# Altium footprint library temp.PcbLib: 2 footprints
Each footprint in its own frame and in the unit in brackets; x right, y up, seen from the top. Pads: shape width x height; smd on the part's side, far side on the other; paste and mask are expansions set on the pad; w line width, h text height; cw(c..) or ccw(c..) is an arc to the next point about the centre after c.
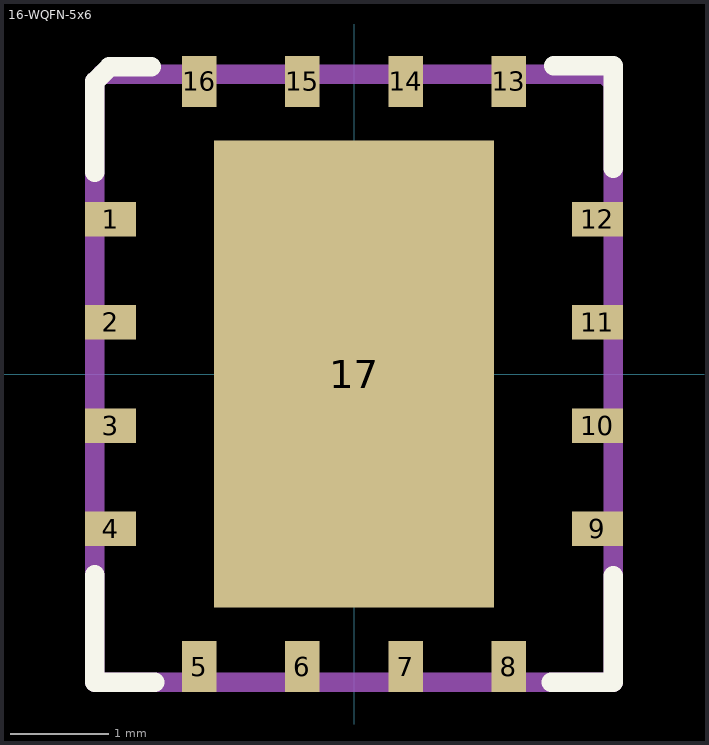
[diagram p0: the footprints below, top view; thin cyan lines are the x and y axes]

## 16-WQFN-5x6 [mm]
pads (17):
  rect 0.52x0.35 smd mask+0.05: 1(-2.475,1.575) 2(-2.475,0.525) 3(-2.475,-0.525) 4(-2.475,-1.575) 9(2.475,-1.575) 10(2.475,-0.525) 11(2.475,0.525) 12(2.475,1.575)
  rect 0.35x0.52 smd mask+0.05: 5(-1.575,-2.975) 6(-0.525,-2.975) 7(0.525,-2.975) 8(1.575,-2.975) 13(1.575,2.975) 14(0.525,2.975) 15(-0.525,2.975) 16(-1.575,2.975)
  rect 2.85x4.75 smd mask+0.05: 17(0,0)
Top Overlay:
  lines w0.2: -2.635,-2.043 -2.635,-3.135 -2.027,-3.135 ; -2.635,2.051 -2.635,2.975 -2.488,3.122 -2.06,3.122 ; 2.004,-3.135 2.635,-3.135 2.635,-2.051 ; 2.032,3.135 2.635,3.135 2.635,2.092
  text "." at -3.3,1.5 h1
Mechanical 1:
  lines w0.2: -2.635,2.975 -2.635,-3.135 2.635,-3.135 2.635,2.962 2.549,3.049 -2.561,3.049
  text ".Designator" at -2.535,-2.868 h0.5
3D body: height 0.8, standoff 0.05, extent -2.635,-3.135 2.635,3.135

## PCBComponent_1 [mm]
